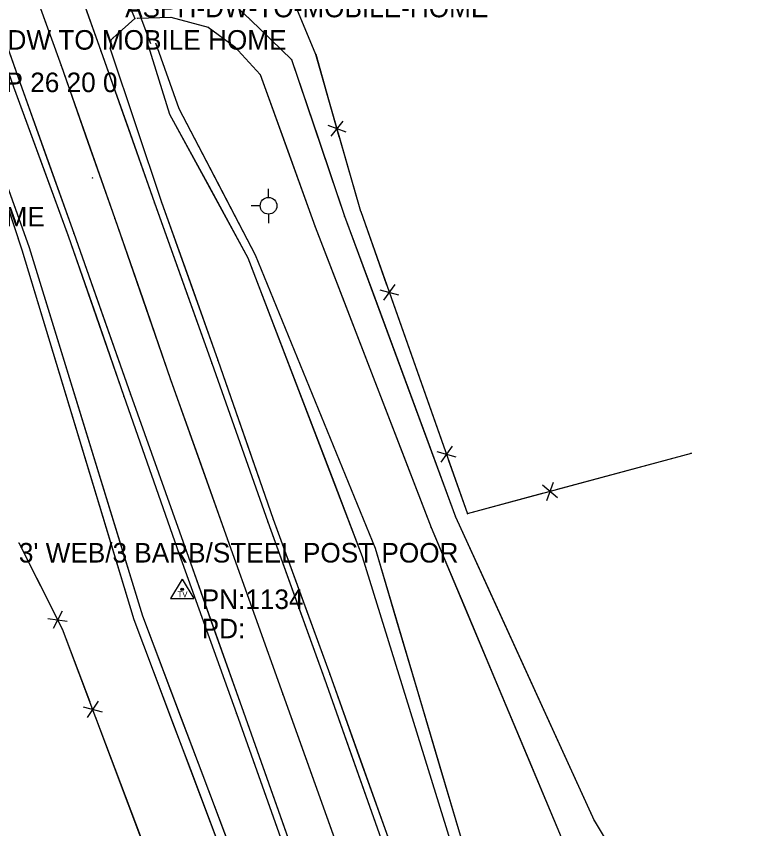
# Model space of a CAD drawing. Extents: x 1050807 to 1053552, y 395828 to 398415.
# Drawn here: x 1052633.5 to 1052820.5, y 396034.9 to 396242.6 of the extents above; entities that cross this region are included whole.
import ezdxf

# ---------------------------------------------------------------- set-up
doc = ezdxf.new("R2010")
doc.units = 0
for name, color, linetype in [('S_BREAKLINE_ANNOT', 7, 'Continuous'), ('S_BUILDING_ANNOT', 7, 'Continuous'), ('S_DITCHLINE', 7, 'Continuous'), ('S_DRIVEWAY', 7, 'Continuous'), ('S_EDGE_PAVEMENT', 7, 'Continuous'), ('S_FENCE', 7, 'Continuous'), ('S_FENCE_ANNOT', 7, 'Continuous'), ('S_MSC_PT_SYM', 7, 'Continuous'), ('S_PAVEMENT_CROWN', 7, 'Continuous'), ('S_RDW_PT_SYM', 7, 'Continuous'), ('S_SECONDARY_CTL', 7, 'Continuous'), ('S_SECONDARY_CTL_ANNOT', 7, 'Continuous'), ('S_SHOULDER', 7, 'Continuous'), ('S_SIDE_DRAIN', 7, 'Continuous'), ('S_SIDE_DRAIN_ANNOT', 7, 'Continuous'), ('S_SURVEY_TEXT_ANNOT', 7, 'Continuous'), ('S_UTILITY_POLE', 7, 'Continuous'), ('S_UTL_PT_SYM', 7, 'Continuous')]:
    doc.layers.add(name, color=color, linetype=linetype)

msp = doc.modelspace()

# ---------------------------------------------------------------- linework, layer by layer
at = {"layer": 'S_DITCHLINE'}
for p, q in [((1052667.19, 396235.17), (1052672.63, 396217.62)), ((1052669.02, 396235.8), (1052675.04, 396219.02)), ((1052620.07, 396227.58), (1052634.89, 396182.92)), ((1052620.81, 396227.93), (1052636.76, 396183.53)), ((1052675.04, 396219.02), (1052694.54, 396181.62)), ((1052672.63, 396217.62), (1052692.68, 396180.88)), ((1052636.76, 396183.53), (1052665.73, 396089.35)), ((1052634.89, 396182.92), (1052663.51, 396088.42)), ((1052694.54, 396181.62), (1052725.19, 396106.59)), ((1052692.68, 396180.88), (1052721.92, 396104.47)), ((1052725.19, 396106.59), (1052747.18, 396032.38)), ((1052721.92, 396104.47), (1052744.4, 396031.88)), ((1052663.51, 396088.42), (1052703.24, 395983.02)), ((1052665.73, 396089.35), (1052705.46, 395984.05))]:
    msp.add_line(p, q, dxfattribs=at)
for points in [[(1052667.19, 396235.17), (1052672.63, 396217.62), (1052682.66, 396199.25), (1052692.68, 396180.88), (1052699.99, 396161.78), (1052707.3, 396142.68), (1052714.61, 396123.58), (1052721.92, 396104.47), (1052727.54, 396086.32), (1052733.16, 396068.18), (1052738.78, 396050.03), (1052744.4, 396031.88), (1052749.9, 396011.56), (1052755.39, 395991.25), (1052760.89, 395970.94), (1052766.38, 395950.62), (1052770.97, 395937.73), (1052775.55, 395924.84), (1052780.13, 395911.95), (1052784.72, 395899.06), (1052791.2, 395881.32), (1052797.68, 395863.58), (1052804.16, 395845.85), (1052810.64, 395828.11)], [(1052669.02, 396235.8), (1052675.04, 396219.02), (1052684.79, 396200.32), (1052694.54, 396181.62), (1052702.2, 396162.86), (1052709.86, 396144.1), (1052717.52, 396125.35), (1052725.19, 396106.59), (1052730.68, 396088.04), (1052736.18, 396069.48), (1052741.68, 396050.93), (1052747.18, 396032.38), (1052752.87, 396012.01), (1052758.56, 395991.64), (1052764.26, 395971.28), (1052769.95, 395950.91), (1052774.46, 395938.14), (1052778.98, 395925.37), (1052783.49, 395912.6), (1052788.01, 395899.83), (1052794.16, 395882.03), (1052800.32, 395864.23), (1052806.48, 395846.43), (1052812.63, 395828.64)], [(1052620.07, 396227.58), (1052627.48, 396205.25), (1052634.89, 396182.92), (1052642.05, 396159.3), (1052649.2, 396135.67), (1052656.36, 396112.05), (1052663.51, 396088.42), (1052668.48, 396075.25), (1052673.44, 396062.07), (1052678.41, 396048.9), (1052683.38, 396035.72), (1052688.34, 396022.55), (1052693.31, 396009.37), (1052698.27, 395996.19), (1052703.24, 395983.02), (1052710.64, 395963.11), (1052718.05, 395943.2), (1052725.45, 395923.3), (1052732.85, 395903.39), (1052737.44, 395889.76), (1052742.03, 395876.12), (1052746.61, 395862.49), (1052751.2, 395848.85)], [(1052620.81, 396227.93), (1052628.79, 396205.73), (1052636.76, 396183.53), (1052644, 396159.99), (1052651.24, 396136.44), (1052658.48, 396112.9), (1052665.73, 396089.35), (1052670.69, 396076.19), (1052675.66, 396063.03), (1052680.63, 396049.86), (1052685.59, 396036.7), (1052690.56, 396023.54), (1052695.53, 396010.38), (1052700.49, 395997.21), (1052705.46, 395984.05), (1052713.07, 395964.14), (1052720.69, 395944.23), (1052728.3, 395924.32), (1052735.92, 395904.41), (1052740.3, 395890.61), (1052744.69, 395876.8), (1052749.07, 395863), (1052753.46, 395849.2)]]:
    msp.add_lwpolyline(points, dxfattribs=at)
at = {"layer": 'S_DRIVEWAY'}
for p, q in [((1052658.9, 396253.46), (1052663.79, 396242.04)), ((1052686.97, 396247.75), (1052693.36, 396241.69)), ((1052663.79, 396242.04), (1052658.16, 396237.04)), ((1052664.49, 396242.14), (1052673.01, 396242.35)), ((1052673.01, 396242.35), (1052682.55, 396239.86)), ((1052693.36, 396241.69), (1052703.81, 396231.56)), ((1052682.55, 396239.86), (1052689.21, 396234.92)), ((1052658.16, 396237.04), (1052657.67, 396236.53)), ((1052689.21, 396234.92), (1052695.83, 396227.71)), ((1052703.81, 396231.56), (1052717.4, 396191.5)), ((1052695.83, 396227.71), (1052709.91, 396188.79)), ((1052717.4, 396191.5), (1052745.75, 396114.65)), ((1052709.91, 396188.79), (1052739.52, 396111.91)), ((1052745.75, 396114.65), (1052781.19, 396037.02)), ((1052739.52, 396111.91), (1052772.8, 396032.74)), ((1052781.19, 396037.02), (1052810.9, 395987.58))]:
    msp.add_line(p, q, dxfattribs=at)
for points in [[(1052650.63, 396255.24), (1052655.68, 396253.09), (1052658.9, 396253.46), (1052663.79, 396242.04), (1052658.16, 396237.04), (1052657.67, 396236.53)], [(1052659.6, 396252.65), (1052670.75, 396253.48), (1052686.97, 396247.75), (1052693.36, 396241.69), (1052703.81, 396231.56), (1052710.61, 396211.53), (1052717.4, 396191.5), (1052724.49, 396172.29), (1052731.58, 396153.08), (1052738.66, 396133.87), (1052745.75, 396114.65), (1052754.61, 396095.25), (1052763.47, 396075.84), (1052772.33, 396056.43), (1052781.19, 396037.02), (1052788.62, 396024.66), (1052796.05, 396012.3), (1052803.47, 395999.94), (1052810.9, 395987.58), (1052815.52, 395970.22), (1052820.46, 395954.63), (1052808.41, 395951.52)], [(1052664.49, 396242.14), (1052673.01, 396242.35), (1052682.55, 396239.86), (1052689.21, 396234.92), (1052695.83, 396227.71), (1052702.87, 396208.25), (1052709.91, 396188.79), (1052717.31, 396169.57), (1052724.71, 396150.35), (1052732.11, 396131.13), (1052739.52, 396111.91), (1052747.84, 396092.12), (1052756.16, 396072.33), (1052764.48, 396052.53), (1052772.8, 396032.74), (1052778.89, 396019.43), (1052784.98, 396006.11), (1052791.06, 395992.8), (1052797.15, 395979.49), (1052804.07, 395963.29), (1052808.41, 395951.52)]]:
    msp.add_lwpolyline(points, dxfattribs=at)
at = {"layer": 'S_EDGE_PAVEMENT'}
for p, q in [((1052644.72, 396263.02), (1052655.12, 396233.76)), ((1052623.98, 396255.21), (1052634.42, 396225.5)), ((1052655.12, 396233.76), (1052668.81, 396194.91)), ((1052634.42, 396225.5), (1052648.17, 396187.15)), ((1052668.81, 396194.91), (1052683.44, 396153.91)), ((1052648.17, 396187.15), (1052662.63, 396146)), ((1052683.44, 396153.91), (1052697.8, 396113.32)), ((1052662.63, 396146), (1052676.99, 396105.79)), ((1052697.8, 396113.32), (1052712.3, 396073.21)), ((1052676.99, 396105.79), (1052691.54, 396064.73)), ((1052712.3, 396073.21), (1052726.77, 396032.18)), ((1052691.54, 396064.73), (1052705.54, 396025.11))]:
    msp.add_line(p, q, dxfattribs=at)
for points in [[(1052623.98, 396255.21), (1052629.2, 396240.35), (1052634.42, 396225.5), (1052641.29, 396206.33), (1052648.17, 396187.15), (1052655.4, 396166.58), (1052662.63, 396146), (1052669.81, 396125.89), (1052676.99, 396105.79), (1052684.26, 396085.26), (1052691.54, 396064.73), (1052698.54, 396044.92), (1052705.54, 396025.11), (1052713.26, 396003.75), (1052720.98, 395982.38), (1052728.49, 395960.93), (1052736.01, 395939.48), (1052742.94, 395919.92), (1052749.87, 395900.35), (1052754.46, 395887.56), (1052759.05, 395874.76), (1052766.38, 395854.19)], [(1052649.92, 396248.39), (1052655.12, 396233.76), (1052661.96, 396214.34), (1052668.81, 396194.91), (1052676.12, 396174.41), (1052683.44, 396153.91), (1052690.62, 396133.61), (1052697.8, 396113.32), (1052705.05, 396093.26), (1052712.3, 396073.21), (1052719.54, 396052.69), (1052726.77, 396032.18), (1052734.08, 396011.52), (1052741.39, 395990.85), (1052749.16, 395969.07), (1052756.93, 395947.29), (1052764.11, 395927.55), (1052771.28, 395907.81), (1052775.95, 395894.59), (1052780.63, 395881.38), (1052787.73, 395861.44)]]:
    msp.add_lwpolyline(points, dxfattribs=at)
at = {"layer": 'S_FENCE'}
for p, q in [((1052716.04, 396211.82), (1052710.12, 396232.83)), ((1052717.78, 396213.01), (1052713.17, 396214.73)), ((1052713.96, 396211.98), (1052717, 396215.77)), ((1052721.51, 396192.74), (1052748.79, 396115.44)), ((1052726.41, 396172.71), (1052731.22, 396171.38)), ((1052730.27, 396174.08), (1052727.36, 396170.01)), ((1052741.01, 396131.32), (1052745.83, 396129.98)), ((1052744.87, 396132.68), (1052741.96, 396128.62)), ((1052748.79, 396115.49), (1052806.05, 396130.9)), ((1052769.09, 396118.83), (1052770.79, 396123.53)), ((1052768.03, 396122.79), (1052771.85, 396119.57)), ((1052634.13, 396107.95), (1052645.22, 396085.99)), ((1052645.22, 396090.53), (1052642.86, 396086.12)), ((1052641.56, 396088.68), (1052646.51, 396087.97)), ((1052645.22, 396085.99), (1052684.41, 395981.91)), ((1052654.37, 396067.49), (1052651.55, 396063.37)), ((1052650.54, 396066.05), (1052655.38, 396064.81))]:
    msp.add_line(p, q, dxfattribs=at)
for points in [[(1052721.51, 396192.74), (1052710.07, 396232.83), (1052702.19, 396251.73), (1052696.92, 396265.33)], [(1052714.93, 396215.79), (1052710.07, 396232.83), (1052702.19, 396251.73), (1052701.55, 396253.39)], [(1052721.51, 396192.74), (1052716.03, 396211.95)], [(1052721.51, 396192.74), (1052728.15, 396173.93)], [(1052729.48, 396170.16), (1052742.76, 396132.53)], [(1052743.9, 396129.3), (1052748.79, 396115.44)], [(1052771.86, 396121.7), (1052806.05, 396130.9)], [(1052748.79, 396115.49), (1052768.02, 396120.66)], [(1052634.13, 396107.95), (1052643.14, 396090.11)], [(1052644.94, 396086.54), (1052645.22, 396085.99)], [(1052645.22, 396085.99), (1052652.26, 396067.3)], [(1052653.66, 396063.56), (1052667.74, 396026.19)]]:
    msp.add_lwpolyline(points, dxfattribs=at)
at = {"layer": 'S_MSC_PT_SYM'}
for points in [[(1052710.07, 396232.83), (1052710.07, 396232.88), (1052710.07, 396232.83), (1052710.02, 396232.83), (1052710.07, 396232.83), (1052710.07, 396232.78), (1052710.07, 396232.83), (1052710.12, 396232.83)], [(1052721.51, 396192.74), (1052721.51, 396192.79), (1052721.51, 396192.74), (1052721.46, 396192.74), (1052721.51, 396192.74), (1052721.51, 396192.69), (1052721.51, 396192.74), (1052721.56, 396192.74)], [(1052806, 396130.9), (1052806, 396130.95), (1052806, 396130.9), (1052805.95, 396130.9), (1052806, 396130.9), (1052806, 396130.85), (1052806, 396130.9), (1052806.05, 396130.9)], [(1052748.79, 396115.44), (1052748.79, 396115.49), (1052748.79, 396115.44), (1052748.74, 396115.44), (1052748.79, 396115.44), (1052748.79, 396115.39), (1052748.79, 396115.44), (1052748.84, 396115.44)], [(1052634.13, 396107.95), (1052634.13, 396108), (1052634.13, 396107.95), (1052634.08, 396107.95), (1052634.13, 396107.95), (1052634.13, 396107.9), (1052634.13, 396107.95), (1052634.18, 396107.95)], [(1052645.22, 396085.99), (1052645.22, 396086.04), (1052645.22, 396085.99), (1052645.17, 396085.99), (1052645.22, 396085.99), (1052645.22, 396085.94), (1052645.22, 396085.99), (1052645.27, 396085.99)]]:
    msp.add_lwpolyline(points, dxfattribs=at)
at = {"layer": 'S_PAVEMENT_CROWN'}
for p, q in [((1052634.39, 396259.26), (1052644.91, 396230.01)), ((1052644.91, 396230.01), (1052658.64, 396190.89)), ((1052658.64, 396190.89), (1052672.91, 396149.79)), ((1052672.91, 396149.79), (1052687.49, 396108.87)), ((1052687.49, 396108.87), (1052701.59, 396069.26)), ((1052701.59, 396069.26), (1052716.29, 396028.33))]:
    msp.add_line(p, q, dxfattribs=at)
msp.add_lwpolyline([(1052639.65, 396244.64), (1052644.91, 396230.01), (1052651.77, 396210.45), (1052658.64, 396190.89), (1052665.78, 396170.34), (1052672.91, 396149.79), (1052680.2, 396129.33), (1052687.49, 396108.87), (1052694.54, 396089.07), (1052701.59, 396069.26), (1052708.94, 396048.8), (1052716.29, 396028.33), (1052723.67, 396007.28), (1052731.06, 395986.23), (1052738.71, 395964.6), (1052746.35, 395942.97), (1052753.3, 395923.48), (1052760.26, 395904), (1052764.96, 395890.95), (1052769.66, 395877.9), (1052777.01, 395857.04)], dxfattribs=at)
at = {"layer": 'S_RDW_PT_SYM'}
for points in [[(1052663.79, 396242.04), (1052663.79, 396242.09), (1052663.79, 396242.04), (1052663.74, 396242.04), (1052663.79, 396242.04), (1052663.79, 396241.99), (1052663.79, 396242.04), (1052663.84, 396242.04)], [(1052664.49, 396242.14), (1052664.49, 396242.19), (1052664.49, 396242.14), (1052664.44, 396242.14), (1052664.49, 396242.14), (1052664.49, 396242.09), (1052664.49, 396242.14), (1052664.54, 396242.14)], [(1052673.01, 396242.35), (1052673.01, 396242.4), (1052673.01, 396242.35), (1052672.96, 396242.35), (1052673.01, 396242.35), (1052673.01, 396242.3), (1052673.01, 396242.35), (1052673.06, 396242.35)], [(1052693.36, 396241.69), (1052693.36, 396241.74), (1052693.36, 396241.69), (1052693.31, 396241.69), (1052693.36, 396241.69), (1052693.36, 396241.64), (1052693.36, 396241.69), (1052693.41, 396241.69)], [(1052682.55, 396239.86), (1052682.55, 396239.91), (1052682.55, 396239.86), (1052682.5, 396239.86), (1052682.55, 396239.86), (1052682.55, 396239.81), (1052682.55, 396239.86), (1052682.6, 396239.86)], [(1052658.16, 396237.04), (1052658.16, 396237.09), (1052658.16, 396237.04), (1052658.11, 396237.04), (1052658.16, 396237.04), (1052658.16, 396236.99), (1052658.16, 396237.04), (1052658.21, 396237.04)], [(1052657.67, 396236.53), (1052657.67, 396236.58), (1052657.67, 396236.53), (1052657.62, 396236.53), (1052657.67, 396236.53), (1052657.67, 396236.48), (1052657.67, 396236.53), (1052657.72, 396236.53)], [(1052657.67, 396236.53), (1052657.67, 396236.58), (1052657.67, 396236.53), (1052657.62, 396236.53), (1052657.67, 396236.53), (1052657.67, 396236.48), (1052657.67, 396236.53), (1052657.72, 396236.53)], [(1052655.12, 396233.76), (1052655.12, 396233.81), (1052655.12, 396233.76), (1052655.07, 396233.76), (1052655.12, 396233.76), (1052655.12, 396233.71), (1052655.12, 396233.76), (1052655.17, 396233.76)], [(1052657.5, 396234.32), (1052657.5, 396234.37), (1052657.5, 396234.32), (1052657.45, 396234.32), (1052657.5, 396234.32), (1052657.5, 396234.27), (1052657.5, 396234.32), (1052657.55, 396234.32)], [(1052689.21, 396234.92), (1052689.21, 396234.97), (1052689.21, 396234.92), (1052689.16, 396234.92), (1052689.21, 396234.92), (1052689.21, 396234.87), (1052689.21, 396234.92), (1052689.26, 396234.92)], [(1052703.81, 396231.56), (1052703.81, 396231.61), (1052703.81, 396231.56), (1052703.76, 396231.56), (1052703.81, 396231.56), (1052703.81, 396231.51), (1052703.81, 396231.56), (1052703.86, 396231.56)], [(1052644.91, 396230.01), (1052644.91, 396230.06), (1052644.91, 396230.01), (1052644.86, 396230.01), (1052644.91, 396230.01), (1052644.91, 396229.96), (1052644.91, 396230.01), (1052644.96, 396230.01)], [(1052695.83, 396227.71), (1052695.83, 396227.76), (1052695.83, 396227.71), (1052695.78, 396227.71), (1052695.83, 396227.71), (1052695.83, 396227.66), (1052695.83, 396227.71), (1052695.88, 396227.71)], [(1052634.42, 396225.5), (1052634.42, 396225.55), (1052634.42, 396225.5), (1052634.37, 396225.5), (1052634.42, 396225.5), (1052634.42, 396225.45), (1052634.42, 396225.5), (1052634.47, 396225.5)], [(1052668.81, 396194.91), (1052668.81, 396194.96), (1052668.81, 396194.91), (1052668.76, 396194.91), (1052668.81, 396194.91), (1052668.81, 396194.86), (1052668.81, 396194.91), (1052668.86, 396194.91)], [(1052670.62, 396195.12), (1052670.62, 396195.17), (1052670.62, 396195.12), (1052670.57, 396195.12), (1052670.62, 396195.12), (1052670.62, 396195.07), (1052670.62, 396195.12), (1052670.67, 396195.12)], [(1052717.4, 396191.5), (1052717.4, 396191.55), (1052717.4, 396191.5), (1052717.35, 396191.5), (1052717.4, 396191.5), (1052717.4, 396191.45), (1052717.4, 396191.5), (1052717.45, 396191.5)], [(1052658.64, 396190.89), (1052658.64, 396190.94), (1052658.64, 396190.89), (1052658.59, 396190.89), (1052658.64, 396190.89), (1052658.64, 396190.84), (1052658.64, 396190.89), (1052658.69, 396190.89)], [(1052648.17, 396187.15), (1052648.17, 396187.2), (1052648.17, 396187.15), (1052648.12, 396187.15), (1052648.17, 396187.15), (1052648.17, 396187.1), (1052648.17, 396187.15), (1052648.22, 396187.15)], [(1052709.91, 396188.79), (1052709.91, 396188.84), (1052709.91, 396188.79), (1052709.86, 396188.79), (1052709.91, 396188.79), (1052709.91, 396188.74), (1052709.91, 396188.79), (1052709.96, 396188.79)], [(1052646.77, 396186.52), (1052646.77, 396186.57), (1052646.77, 396186.52), (1052646.72, 396186.52), (1052646.77, 396186.52), (1052646.77, 396186.47), (1052646.77, 396186.52), (1052646.82, 396186.52)], [(1052685.02, 396154.66), (1052685.02, 396154.71), (1052685.02, 396154.66), (1052684.97, 396154.66), (1052685.02, 396154.66), (1052685.02, 396154.61), (1052685.02, 396154.66), (1052685.07, 396154.66)], [(1052683.44, 396153.91), (1052683.44, 396153.96), (1052683.44, 396153.91), (1052683.39, 396153.91), (1052683.44, 396153.91), (1052683.44, 396153.86), (1052683.44, 396153.91), (1052683.49, 396153.91)], [(1052672.91, 396149.79), (1052672.91, 396149.84), (1052672.91, 396149.79), (1052672.86, 396149.79), (1052672.91, 396149.79), (1052672.91, 396149.74), (1052672.91, 396149.79), (1052672.96, 396149.79)], [(1052662.63, 396146), (1052662.63, 396146.05), (1052662.63, 396146), (1052662.58, 396146), (1052662.63, 396146), (1052662.63, 396145.95), (1052662.63, 396146), (1052662.68, 396146)], [(1052660.94, 396145.49), (1052660.94, 396145.54), (1052660.94, 396145.49), (1052660.89, 396145.49), (1052660.94, 396145.49), (1052660.94, 396145.44), (1052660.94, 396145.49), (1052660.99, 396145.49)], [(1052745.75, 396114.65), (1052745.75, 396114.7), (1052745.75, 396114.65), (1052745.7, 396114.65), (1052745.75, 396114.65), (1052745.75, 396114.6), (1052745.75, 396114.65), (1052745.8, 396114.65)], [(1052697.8, 396113.32), (1052697.8, 396113.37), (1052697.8, 396113.32), (1052697.75, 396113.32), (1052697.8, 396113.32), (1052697.8, 396113.27), (1052697.8, 396113.32), (1052697.85, 396113.32)], [(1052699.17, 396114.07), (1052699.17, 396114.12), (1052699.17, 396114.07), (1052699.12, 396114.07), (1052699.17, 396114.07), (1052699.17, 396114.02), (1052699.17, 396114.07), (1052699.22, 396114.07)], [(1052739.52, 396111.91), (1052739.52, 396111.96), (1052739.52, 396111.91), (1052739.47, 396111.91), (1052739.52, 396111.91), (1052739.52, 396111.86), (1052739.52, 396111.91), (1052739.57, 396111.91)], [(1052687.49, 396108.87), (1052687.49, 396108.92), (1052687.49, 396108.87), (1052687.44, 396108.87), (1052687.49, 396108.87), (1052687.49, 396108.82), (1052687.49, 396108.87), (1052687.54, 396108.87)], [(1052675.13, 396105.12), (1052675.13, 396105.17), (1052675.13, 396105.12), (1052675.08, 396105.12), (1052675.13, 396105.12), (1052675.13, 396105.07), (1052675.13, 396105.12), (1052675.18, 396105.12)], [(1052676.99, 396105.79), (1052676.99, 396105.84), (1052676.99, 396105.79), (1052676.94, 396105.79), (1052676.99, 396105.79), (1052676.99, 396105.74), (1052676.99, 396105.79), (1052677.04, 396105.79)], [(1052712.3, 396073.21), (1052712.3, 396073.26), (1052712.3, 396073.21), (1052712.25, 396073.21), (1052712.3, 396073.21), (1052712.3, 396073.16), (1052712.3, 396073.21), (1052712.35, 396073.21)], [(1052713.62, 396074.37), (1052713.62, 396074.42), (1052713.62, 396074.37), (1052713.57, 396074.37), (1052713.62, 396074.37), (1052713.62, 396074.32), (1052713.62, 396074.37), (1052713.67, 396074.37)], [(1052701.59, 396069.26), (1052701.59, 396069.31), (1052701.59, 396069.26), (1052701.54, 396069.26), (1052701.59, 396069.26), (1052701.59, 396069.21), (1052701.59, 396069.26), (1052701.64, 396069.26)], [(1052691.54, 396064.73), (1052691.54, 396064.78), (1052691.54, 396064.73), (1052691.49, 396064.73), (1052691.54, 396064.73), (1052691.54, 396064.68), (1052691.54, 396064.73), (1052691.59, 396064.73)], [(1052689.75, 396064.34), (1052689.75, 396064.39), (1052689.75, 396064.34), (1052689.7, 396064.34), (1052689.75, 396064.34), (1052689.75, 396064.29), (1052689.75, 396064.34), (1052689.8, 396064.34)], [(1052781.19, 396037.02), (1052781.19, 396037.07), (1052781.19, 396037.02), (1052781.14, 396037.02), (1052781.19, 396037.02), (1052781.19, 396036.97), (1052781.19, 396037.02), (1052781.24, 396037.02)]]:
    msp.add_lwpolyline(points, dxfattribs=at)
at = {"layer": 'S_SECONDARY_CTL'}
for p, q in [((1052675.88, 396098.68), (1052672.87, 396093.72)), ((1052675.88, 396098.68), (1052678.83, 396093.72)), ((1052672.87, 396093.72), (1052678.83, 396093.72))]:
    msp.add_line(p, q, dxfattribs=at)
for radius in [0.311, 0.183, 0.103]:
    msp.add_circle((1052675.88, 396096.07), radius, dxfattribs=at)
at = {"layer": 'S_SHOULDER'}
for p, q in [((1052657.67, 396236.53), (1052657.5, 396234.32)), ((1052657.5, 396234.32), (1052670.62, 396195.12)), ((1052632.79, 396224.61), (1052646.77, 396186.52)), ((1052670.62, 396195.12), (1052685.02, 396154.66)), ((1052646.77, 396186.52), (1052660.94, 396145.49)), ((1052685.02, 396154.66), (1052699.17, 396114.07)), ((1052660.94, 396145.49), (1052675.13, 396105.12)), ((1052699.17, 396114.07), (1052713.62, 396074.37)), ((1052675.13, 396105.12), (1052689.75, 396064.34)), ((1052713.62, 396074.37), (1052728.52, 396032.59)), ((1052689.75, 396064.34), (1052703.9, 396024.43))]:
    msp.add_line(p, q, dxfattribs=at)
for points in [[(1052657.67, 396236.53), (1052657.5, 396234.32), (1052664.06, 396214.72), (1052670.62, 396195.12), (1052677.82, 396174.89), (1052685.02, 396154.66), (1052692.1, 396134.37), (1052699.17, 396114.07), (1052706.4, 396094.22), (1052713.62, 396074.37), (1052721.07, 396053.48), (1052728.52, 396032.59), (1052735.74, 396011.99), (1052742.95, 395991.39), (1052750.76, 395969.45), (1052758.57, 395947.51), (1052765.5, 395927.88), (1052772.43, 395908.25), (1052777.18, 395894.88), (1052781.93, 395881.51), (1052789.15, 395861.89)], [(1052629.12, 396231.28), (1052630.77, 396230.22), (1052632.79, 396224.61), (1052639.78, 396205.57), (1052646.77, 396186.52), (1052653.85, 396166), (1052660.94, 396145.49), (1052668.04, 396125.3), (1052675.13, 396105.12), (1052682.44, 396084.73), (1052689.75, 396064.34), (1052696.82, 396044.39), (1052703.9, 396024.43), (1052711.34, 396003.05), (1052718.79, 395981.67), (1052726.33, 395960.3), (1052733.88, 395938.93), (1052740.96, 395919.42), (1052748.04, 395899.9), (1052752.59, 395886.84), (1052757.15, 395873.79), (1052764.55, 395853.95)]]:
    msp.add_lwpolyline(points, dxfattribs=at)
at = {"layer": 'S_SIDE_DRAIN'}
msp.add_line((1052659.18, 396258.74), (1052667.74, 396235.64), dxfattribs=at)
at = {"layer": 'S_UTILITY_POLE'}
for p, q in [((1052697.95, 396196.28), (1052697.95, 396198.53)), ((1052695.85, 396194.15), (1052693.53, 396194.15)), ((1052698.02, 396189.73), (1052698.02, 396192.06))]:
    msp.add_line(p, q, dxfattribs=at)
msp.add_circle((1052697.95, 396194.17), 2.13, dxfattribs=at)
at = {"layer": 'S_UTL_PT_SYM'}
msp.add_lwpolyline([(1052652.93, 396201.3), (1052652.93, 396201.35), (1052652.93, 396201.3), (1052652.88, 396201.3), (1052652.93, 396201.3), (1052652.93, 396201.25), (1052652.93, 396201.3), (1052652.98, 396201.3)], dxfattribs=at)

# ---------------------------------------------------------------- texts
at = {"layer": 'S_BREAKLINE_ANNOT'}
msp.add_text("3' WEB/3 BARB/STEEL POST POOR", height=5, dxfattribs=at).set_placement((1052634.13, 396102.95))
at = {"layer": 'S_BUILDING_ANNOT'}
msp.add_text('MOBILE  HOME', height=5, dxfattribs=at).set_placement((1052591.72, 396188.88))
at = {"layer": 'S_FENCE_ANNOT'}
msp.add_text("3' WEB/3 BARB/STEEL POST POOR", height=5, dxfattribs=at).set_placement((1052634.13, 396102.95))
at = {"layer": 'S_SECONDARY_CTL'}
msp.add_text('TV', height=1.5, dxfattribs=at).set_placement((1052674.68, 396094.06))
at = {"layer": 'S_SECONDARY_CTL_ANNOT'}
for s, p in [('PN:1134', (1052680.88, 396091.07)), ('PD:', (1052680.88, 396083.57))]:
    msp.add_text(s, height=5, dxfattribs=at).set_placement(p)
at = {"layer": 'S_SIDE_DRAIN_ANNOT'}
msp.add_text('CMP 26 20 0', height=5, dxfattribs=at).set_placement((1052620.32, 396223.22))
at = {"layer": 'S_SURVEY_TEXT_ANNOT'}
for s, p in [('ASPH-DW-TO-MOBILE-HOME', (1052661.29, 396242.36)), ('ASPH DW TO MOBILE HOME', (1052611.16, 396234.08))]:
    msp.add_text(s, height=5, dxfattribs=at).set_placement(p)

doc.saveas('drawing.dxf')
